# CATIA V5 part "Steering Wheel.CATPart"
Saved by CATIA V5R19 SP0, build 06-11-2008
Part number: Steering Wheel
Bounding box of the stored display mesh (mm): x -360.883 to 360.883, y -360.883 to 360.883, z 0 to 350
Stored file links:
  D:\Shriniwas\v5_r19\c16_CAT_v5r19\c16_Part\Stearing msm\Steering Wheel.CATPart
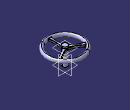
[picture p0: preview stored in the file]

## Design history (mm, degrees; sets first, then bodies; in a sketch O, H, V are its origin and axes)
Body1 (main body)
  Sketch1 on xy-plane, origin (0, 0, 0), H (1, 0, 0), V (0, 1, 0)
    circle A1 centre (0, 0) radius 50
    radius A1 = 50
  Pad1: profile Sketch1, direction (0, 0, 1), length 350
  Plane1: type Offset, Offset 50, RefPlane end face of Pad1
  Sketch2 on Plane1, origin (0, 0, 300), H (1, 0, 0), V (0, -1, 0)
    arc A1 centre (-620.9475, 180) radius 600 from (-40, 30) to (-40, 330) ccw
    point P1 (-620.9475, 180)
    point P2 (-40, 30)
    point P3 (-40, 330)
    reference projected circle E1 centre (0, 0) radius 50 from edge [start face of Pad1 | face of Pad1 from Sketch1.A1]
    construction line L1 (-40, 30) -> (-40, 330)
    point P4 (40, 330)
    point P5 (40, 30)
    arc A2 centre (620.9475, 180) radius 600 from (40, 30) to (40, 330) cw
    line L2 (-40, 30) -> (40, 30)
    line L3 (-40, 330) -> (40, 330)
    radius A1 = 600
    length L1 = 300
    distance H P1 = 180
    coincidence: P2 E1
    vertical: L1 V
    symmetry: P3 P4 V, P2 P5 V, A1 A2 V
    horizontal: L2 H, L3 H
  Pad2: profile Sketch2, direction (0, 0, -1), length 20, mirrored extent
  Fillet1: radius 7, on edge [start face of Pad2 | face of Pad2 from Sketch2.A1]; edge [face of Pad2 from Sketch2.A1 | end face of Pad2]; edge [face of Pad2 from Sketch2.A2 | end face of Pad2]; edge [start face of Pad2 | face of Pad2 from Sketch2.A2]; edge [face of Pad2 from Sketch2.A2 | face of Pad1 from Sketch1.A1]; edge [end face of Pad2 | face of Pad1 from Sketch1.A1]; edge [face of Pad1 from Sketch1.A1 | face of Pad2 from Sketch2.A1]; edge [face of Pad1 from Sketch1.A1 | start face of Pad2]
  CircPattern1: of Pad2, instances 3, angular step 120 {= 360.0*1 deg/CircPattern1.AngularNumber}, axis from face of Pad1 from Sketch1.A1
  Fillet2: radius 7, on edge [face of CircPattern1 | face of CircPattern1] (x2); face of CircPattern1 (x10)
  Sketch3 on yz-plane, origin (0, 0, 0), H (0, 1, 0), V (0, 0, 1)
    point P1 (-330, 300)
    ellipse A1 centre (-330, 300) semi-axes 37.5, 30.9839 rotation 90
    reference projected line E1 (-330, 320) -> (-330, 280) from edge [face of Pad2 from Sketch2.L3 | face of Pad2 from Sketch2.A2]
    reference projected line E2 (-49.5784, 320) -> (-330, 320) from edge [start face of Pad2 | face of Fillet1]
    distance P1 E2 = 20
    "Radius" A1 = 37.5
    coincidence: P1 E1
  Shaft1: profile Sketch3, axis axis of face of Pad1 from Sketch1.A1, angle 360
  Fillet3: radius 7, on face of Shaft1 from Sketch3.A1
